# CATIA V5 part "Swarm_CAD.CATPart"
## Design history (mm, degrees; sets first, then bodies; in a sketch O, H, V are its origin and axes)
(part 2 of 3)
  Pad35: profile Sketch46, direction (0, -1, 0), length 15, mirrored extent
  Mirror19: of Pad35, about zx-plane
  Sketch47 on face of Mirror7, origin (0, 0, -275), H (1, 0, 0), V (0, -1, 0)
    line L1 (-1850, 565) -> (-1840, 565)
    line L2 (-1840, 565) -> (-1840, -565)
    line L3 (-1840, -565) -> (-1850, -565)
    line L4 (-1850, -565) -> (-1850, 565)
    point P2 (-1840, 565)
    point P3 (-1840, -565)
    reference projected line E1 (-2000, 665) -> (-2000, 406) from edge [end face of Pad1 | face of Mirror7]
    reference projected line E3 (2945.11, -665) -> (-2000, -665) from edge [face of Mirror7 | face of Pad28]
    reference projected line E4 (2945.11, 665) -> (-2000, 665) from edge [face of Pad28 | face of Mirror7]
    distance L4 E1 = 150
    distance L2 L4 = 10
    distance P3 E3 = 100
    distance P2 E4 = 100
    horizontal: L1 H, L3 H
    vertical: L2 V, L4 V
  Pad36: profile Sketch47, direction (0, 0, -1), length 60
  Sketch48 on face of Mirror17, origin (0, 0, -315), H (1, 0, 0), V (0, -1, 0)
    line L1 (-1750, -660) -> (-1750, -565)
    line L2 (-1750, -565) -> (-2040, -565)
    line L3 (-2040, -565) -> (-2040, -665)
    line L4 (-2040, -665) -> (-1750, -665)
    point P5 (-1750, -665)
    line L5 (-1750, -665) -> (-1750, -660)
    reference projected line E1 (-2000, -406) -> (-2000, -665) from edge [end face of Pad1 | face of Mirror7]
    reference projected line E4 (2945.11, -665) -> (-2000, -665) from edge [face of Mirror7 | face of Pad28]
    reference projected line E5 (-2000, -665) -> (-2000, -605) from edge [start face of Pad28 | face of Mirror17]
    reference projected line E6 (2945.11, -665) -> (-2000, -665) from edge [face of Mirror7 | face of Pad28]
    distance L3 E1 = 40
    distance L2 E4 = 100
    distance L1 E5 = 250
    distance L4 E6 = 0
    vertical: L1 V, L3 V
    horizontal: L2 H, L4 H
    coincidence: P5 L1
    parallelism: L5 L1
  Pad37: profile Sketch48, direction (0, 0, 1), length 81
  Mirror20: of Pad37, about zx-plane
  Sketch49 on face of Pad37, origin (0, 665, 0), H (-1, 0, 0), V (0, 0, 1)
    point P1 (1750, -275)
    line L1 (1750, -275) -> (1750, -315)
    line L2 (1750, -315) -> (1819.282, -315)
    line L3 (1819.282, -315) -> (1750, -275)
    reference projected line E1 (1880, -315) -> (1750, -315) from edge [face of Pad37 | face of Pad37]
    reference projected line E2 (-2945.11, -275) -> (2000, -275) from edge [face of Mirror7 | face of Pad37]
    reference projected line E3 (1750, -315) -> (1750, -234) from edge [face of Pad37 | face of Pad37 from Sketch48.L5]
    distance L2 E1 = 0
    distance P1 E2 = 0
    angle L1 L3 = 60
    vertical: L1 V
    horizontal: L2 H
    coincidence: L1 E3
  Pocket11: profile Sketch49, direction (0, -1, 0), up to face of Mirror20
  Plane5: type Offset, RefPlane end face of Pad1, Offset 60
  Sketch50 on Plane5, origin (-1940, 0, 0), H (0, 1, 0), V (0, 0, 1)
    line L1 (161.8482, -275) -> (149.7238, -282)
    line L2 (149.7238, -282) -> (147, -360)
    point P3 (147, -360)
    line L3 (147, -360) -> (147, -275)
    line L4 (147, -275) -> (161.8482, -275)
    reference projected line E1 (-665, -275) -> (-406, -275) from edge [end face of Pad1 | face of Mirror7]
    reference projected line E3 (-665, -275) -> (-406, -275) from edge [end face of Pad1 | face of Mirror7]
    axis line L5 (147, -270) -> (147, -400)
    point P5 (147, -270)
    distance L4 E1 = 0
    angle L2 L3 = 2
    angle L1 L4 = 30
    distance P3 E3 = 85
    length L1 = 14
    distance L3 V = 147
    vertical: L3 V, L5 V
    horizontal: L4 H
    coincidence: P5 L3
  Shaft1: profile Sketch50, axis Sketch50.L5, angle 360
  Mirror21: of Shaft1, about zx-plane
  Sketch51 on face of Mirror7, origin (0, 0, -275), H (1, 0, 0), V (0, -1, 0)
    line L1 (-1678, 31.5) -> (-1615, 31.5)
    line L2 (-1615, 31.5) -> (-1615, -31.5)
    line L3 (-1615, -31.5) -> (-1678, -31.5)
    line L4 (-1678, -31.5) -> (-1678, 31.5)
    reference projected line E1 (-2000, 665) -> (-2000, 406) from edge [end face of Pad1 | face of Mirror7]
    distance L1 L3 = 63
    distance L2 L4 = 63
    distance L4 E1 = 322
    distance L3 H = 31.5
    horizontal: L1 H, L3 H
    vertical: L2 V, L4 V
  Pad38: profile Sketch51, direction (0, 0, -1), length 50
  Chamfer5: length 50, angle 6, on edge [face of Pad38 from Sketch51.L2 | end face of Pad38]; edge [face of Pad38 from Sketch51.L4 | end face of Pad38]
  Plane6: type Offset, RefPlane face of Pad38 from Sketch51.L3, Offset 31.5
  Sketch52 on Plane6, origin (0, 0, 0), H (1, 0, 0), V (0, 0, 1)
    point P1 (-1646.5, -325)
    line L1 (-1646.5, -325) -> (-1646.5, -521)
    line L2 (-1646.5, -521) -> (-1628.5, -521)
    line L3 (-1628.5, -521) -> (-1621.5, -325)
    line L4 (-1621.5, -325) -> (-1646.5, -325)
    reference projected line E1 (-1615, -325) -> (-1678, -325) from edge [face of Pad38 from Sketch51.L1 | end face of Pad38]
    reference projected point E2 (-1678, -275) from vertex [face of Pad38 from Sketch51.L1 | face of Chamfer5 | face of Mirror7]
    reference projected line E3 (-1615, -275) -> (-1678, -275) from edge [face of Mirror7 | face of Pad38 from Sketch51.L1]
    axis line L5 (-1646.5, -300) -> (-1646.5, -600)
    point P5 (-1646.5, -300)
    distance L4 E1 = 0
    length L2 = 18
    distance P1 E2 H = 31.5
    distance L2 E3 = 246
    length L4 = 25
    vertical: L1 V, L5 V
    horizontal: L2 H, L4 H
    coincidence: P5 L1
  Shaft2: profile Sketch52, axis Sketch52.L5, angle 360
  Plane7: type Offset, RefPlane face of Mirror7, Offset 173, reversed
  Sketch53 on Plane7, origin (0, 0, -448), H (1, 0, 0), V (0, 1, 0)
    line L1 (-393, -191.5) -> (-487, -191.5)
    line L2 (-487, -191.5) -> (-487, -238.5)
    line L3 (-487, -238.5) -> (-393, -238.5)
    line L4 (-393, -238.5) -> (-393, -191.5)
    reference projected line E1 (-2000, 406) -> (-2000, 665) from edge [end face of Pad1 | face of Mirror7]
    length L2 = 47
    distance L4 L2 = 94
    distance L2 E1 = 1513
    distance L1 H = 191.5
    horizontal: L1 H, L3 H
    vertical: L2 V, L4 V
  Pad39: profile Sketch53, direction (0, 0, 1), length 300
  Sketch54 on start face of Pad39, origin (0, 0, -448), H (1, 0, 0), V (0, -1, 0)
    line L1 (-483.5, 235) -> (-443.5, 235)
    line L2 (-443.5, 235) -> (-443.5, 195)
    line L3 (-443.5, 195) -> (-483.5, 195)
    line L4 (-483.5, 195) -> (-483.5, 235)
    point P5 (-436.5, 235)
    line L5 (-436.5, 235) -> (-396.5, 235)
    line L6 (-396.5, 235) -> (-396.5, 195)
    line L7 (-396.5, 195) -> (-436.5, 195)
    line L8 (-436.5, 195) -> (-436.5, 235)
    point P7 (-396.5, 195)
    reference projected line E1 (-393, 238.5) -> (-393, 191.5) from edge [start face of Pad39 | face of Pad39 from Sketch53.L4]
    reference projected line E2 (-393, 191.5) -> (-487, 191.5) from edge [start face of Pad39 | face of Pad39 from Sketch53.L1]
    reference projected line E3 (-487, 191.5) -> (-487, 238.5) from edge [start face of Pad39 | face of Pad39 from Sketch53.L2]
    distance L6 E1 = 3.5
    length L8 = 40
    distance L7 E2 = 3.5
    distance L8 L6 = 40
    distance L4 E3 = 3.5
    distance L2 L4 = 40
    horizontal: L1 H, L3 H, L5 H, L7 H
    vertical: L2 V, L4 V, L6 V, L8 V
    coincidence: P5 L1, P7 L3
  Pad40: profile Sketch54, direction (0, 0, -1), length 3
  Plane8: type Offset, RefPlane start face of Pad39, Offset 32
  Sketch55 on Plane8, origin (0, 0, -416), H (1, 0, 0), V (0, 1, 0)
    line L1 (-383, -181.5) -> (-517, -181.5)
    line L2 (-517, -181.5) -> (-517, -248.5)
    line L3 (-517, -248.5) -> (-383, -248.5)
    line L4 (-383, -248.5) -> (-383, -181.5)
    reference projected line E1 (-487, -191.5) -> (-487, -238.5) from edge [start face of Pad39 | face of Pad39 from Sketch53.L2]
    reference projected line E2 (-393, -191.5) -> (-487, -191.5) from edge [start face of Pad39 | face of Pad39 from Sketch53.L1]
    reference projected line E3 (-487, -238.5) -> (-393, -238.5) from edge [start face of Pad39 | face of Pad39 from Sketch53.L3]
    reference projected line E4 (-393, -238.5) -> (-393, -191.5) from edge [start face of Pad39 | face of Pad39 from Sketch53.L4]
    distance L2 E1 = 30
    distance L1 E2 = 10
    distance L3 E3 = 10
    distance L4 E4 = 10
    horizontal: L1 H, L3 H
    vertical: L2 V, L4 V
  Pad41: profile Sketch55, direction (0, 0, 1), length 300
  Chamfer6: length 170, angle 8, on edge [start face of Pad41 | face of Pad41 from Sketch55.L2]
  Sketch56 on face of Mirror20, origin (0, -665, 0), H (1, 0, 0), V (0, 0, 1)
    point P1 (-365, -211)
    line L1 (-365, -211) -> (9, -211)
    point P2 (9, -211)
    line L2 (9, -211) -> (181, -250)
    point P3 (181, -250)
    line L3 (181, -250) -> (753, -250)
    line L4 (753, -250) -> (753, 29)
    line L5 (753, 29) -> (-365, 29)
    line L6 (-365, 29) -> (-365, -211)
    reference projected line E1 (2945.11, -275) -> (-2000, -275) from edge [face of Mirror20 | face of Mirror7]
    reference projected line E2 (-2010, 1) -> (-2010, -315) from edge [face of Pad34 from Sketch44.L3 | end face of Pad34]
    reference projected line E3 (682.5, 452.4746) -> (682.5, -2.8239) from edge [face of Pad2 | face of Pocket5 from Sketch28.L18]
    distance L1 E1 = 64
    distance L3 L1 = 39
    distance P3 P2 H = 172
    length L1 = 374
    distance P1 E2 = 1645
    distance L4 E3 = 70.5
    distance L5 L1 = 240
    horizontal: L1 H, L3 H, L5 H
    vertical: L4 V, L6 V
  Pad42: profile Sketch56, direction (0, 1, 0), length 50
  Mirror22: of Pad42, about zx-plane
  Sketch57 on face of Pad42, origin (0, -665, 0), H (1, 0, 0), V (0, 0, 1)
    line L1 (-780, 21.4391) -> (-780, -232)
    point P2 (-780, -232)
    line L2 (-780, -232) -> (-704, -232)
    point P3 (-704, -232)
    line L3 (-704, -232) -> (90, -71.9015)
    line L4 (90, -71.9015) -> (90, 21.4391)
    line L5 (90, 21.4391) -> (-780, 21.4391)
    reference projected line E1 (2945.11, -275) -> (-2000, -275) from edge [face of Pad42 | face of Mirror7]
    reference projected line E2 (2945.11, -275) -> (-2000, -275) from edge [face of Pad42 | face of Mirror7]
    reference projected point E3 (-679, -275) from vertex [face of Pocket2 from Sketch5.L3 | face of Pad1 from Sketch1.L8 | face of Pocket1 from Sketch4.L1]
    reference projected line E4 (710, 5.0715) -> (-679, -275) from edge [face of Pad42 | face of Pocket2 from Sketch5.L3]
    reference projected line E5 (-24, 30.4391) -> (-209, 30.4391) from edge [face of Pocket5 from Sketch28.L15 | face of Pad2]
    reference projected point E6 (-679, -275) from vertex [face of Pocket2 from Sketch5.L3 | face of Pad1 from Sketch1.L8 | face of Pocket1 from Sketch4.L1]
    distance L2 E2 = 43
    distance P3 E3 H = 25
    distance L4 L1 = 870
    distance L5 E5 = 9
    distance P2 E6 H = 101
    vertical: L1 V, L4 V
    horizontal: L2 H
    parallelism: L5 E1, L3 E4
  Pad43: profile Sketch57, direction (0, -1, 0), length 25
  Mirror23: of Pad43, about zx-plane
  Sketch58 on face of Pad42, origin (0, -665, 0), H (1, 0, 0), V (0, 0, 1)
    line L1 (-1666, -166.5) -> (-1596, -166.5)
    line L2 (-1596, -166.5) -> (-1596, -236.5)
    line L3 (-1596, -236.5) -> (-1666, -236.5)
    line L4 (-1666, -236.5) -> (-1666, -166.5)
    point P5 (-1493.5, -166.5)
    line L5 (-1493.5, -166.5) -> (-1423.5, -166.5)
    line L6 (-1423.5, -166.5) -> (-1423.5, -236.5)
    line L7 (-1423.5, -236.5) -> (-1493.5, -236.5)
    line L8 (-1493.5, -236.5) -> (-1493.5, -166.5)
    point P7 (-1423.5, -236.5)
    point P9 (-1381, -166.5)
    line L9 (-1381, -166.5) -> (-1311, -166.5)
    line L10 (-1311, -166.5) -> (-1311, -236.5)
    line L11 (-1311, -236.5) -> (-1381, -236.5)
    line L12 (-1381, -236.5) -> (-1381, -166.5)
    point P11 (-1311, -236.5)
    reference projected line E1 (-2010, 1) -> (-2010, -315) from edge [face of Pad34 from Sketch44.L3 | end face of Pad34]
    reference projected line E2 (-2010, 1) -> (-2010, -315) from edge [face of Pad34 from Sketch44.L3 | end face of Pad34]
    reference projected line E3 (2945.11, -275) -> (-2000, -275) from edge [face of Pad42 | face of Mirror7]
    line L13 (333, -141.5) -> (403, -141.5)
    line L14 (403, -141.5) -> (403, -211.5)
    line L15 (403, -211.5) -> (333, -211.5)
    line L16 (333, -211.5) -> (333, -141.5)
    line L17 (423, -141.5) -> (493, -141.5)
    line L18 (493, -141.5) -> (493, -211.5)
    line L19 (493, -211.5) -> (423, -211.5)
    line L20 (423, -211.5) -> (423, -141.5)
    point P19 (493, -211.5)
    reference projected line E4 (181, -250) -> (753, -250) from edge [face of Pad42 from Sketch56.L3 | start face of Pad42]
    reference projected line E5 (753, -250) -> (753, 29) from edge [face of Pad42 from Sketch56.L4 | face of Pad42]
    distance L4 E1 = 344
    distance L8 E2 = 516.5
    distance L6 L8 = 70
    distance L2 L4 = 70
    distance L12 L6 = 42.5
    distance L10 L12 = 70
    distance L11 E3 = 38.5
    distance L1 L3 = 70
    distance L15 E4 = 38.5
    distance L13 L15 = 70
    distance L14 L16 = 70
    distance L17 L19 = 70
    distance L20 L18 = 70
    distance L20 L14 = 20
    distance L18 E5 = 260
    horizontal: L1 H, L3 H, L5 H, L7 H, L9 H, L11 H, L13 H, L15 H, L17 H, L19 H
    vertical: L2 V, L4 V, L6 V, L8 V, L10 V, L12 V, L14 V, L16 V, L18 V, L20 V
    coincidence: P5 L1, P7 L3, P9 L1, P11 L3, P19 L15
  Pad44: profile Sketch58, direction (0, -1, 0), length 20
  Mirror24: of Pad44, about zx-plane
  Plane9: type Offset, RefPlane face of Pad42 from Sketch56.L4, Offset 43
  Sketch59 on Plane9, origin (710, 0, 0), H (0, -1, 0), V (0, 0, 1)
    line L1 (615, 5.0715) -> (615, -250)
    line L2 (615, -250) -> (532.5482, -250)
    line L3 (532.5482, -250) -> (209, -14.9285)
    point P4 (209, -14.9285)
    line L4 (209, -14.9285) -> (0, -14.9285)
    point P5 (0, -14.9285)
    line L5 (0, -14.9285) -> (0, 5.0715)
    line L6 (0, 5.0715) -> (615, 5.0715)
    reference projected line E1 (665, -250) -> (615, -250) from edge [face of Pad42 from Sketch56.L3 | face of Pad42 from Sketch56.L4]
    reference projected line E2 (615, -250) -> (615, 29) from edge [end face of Pad42 | face of Pad42 from Sketch56.L4]
    reference projected line E3 (665, 5.0715) -> (-665, 5.0715) from edge [face of Pocket2 from Sketch5.L3 | face of Pocket3 from Sketch6.L4]
    distance L2 E1 = 0
    distance L1 E2 = 0
    distance L6 E3 = 0
    distance L4 L6 = 20
    angle L3 L2 = 36
    distance P4 V = 209
    vertical: L1 V, L5 V
    horizontal: L2 H, L4 H, L6 H
    coincidence: P5 V
  Pad45: profile Sketch59, direction (-1, 0, 0), length 35
  Mirror25: of Pad45, about zx-plane
  Plane10: type Offset, RefPlane face of Pad37, Offset 38
  Sketch60 on Plane10, origin (0, 0, -277), H (1, 0, 0), V (0, 1, 0)
    line L1 (504, 615) -> (354, 615)
    line L2 (354, 615) -> (354, 465)
    line L3 (354, 465) -> (504, 465)
    line L4 (504, 465) -> (504, 615)
    reference projected line E1 (-2000, 406) -> (-2000, 665) from edge [end face of Pad1 | face of Mirror7]
    reference projected line E4 (181, 615) -> (753, 615) from edge [face of Mirror25 | face of Mirror22]
    distance L2 E1 = 2354
    distance L2 L4 = 150
    distance L1 L3 = 150
    distance L1 E4 = 0
    horizontal: L1 H, L3 H
    vertical: L2 V, L4 V
  Pad46: profile Sketch60, direction (0, 0, 1), length 350
  Sketch61 on start face of Pad46, origin (0, 0, -277), H (1, 0, 0), V (0, -1, 0)
    point P1 (428.7804, -474)
    line L1 (428.7804, -474) -> (363, -539.7804)
    point P2 (363, -539.7804)
    line L2 (363, -539.7804) -> (429.2196, -606)
    point P3 (429.2196, -606)
    line L3 (429.2196, -606) -> (495, -540.2196)
    point P4 (495, -540.2196)
    line L4 (495, -540.2196) -> (428.7804, -474)
    reference projected line E1 (504, -615) -> (354, -615) from edge [start face of Pad46 | face of Pad46 from Sketch60.L1]
    reference projected line E2 (354, -465) -> (504, -465) from edge [start face of Pad46 | face of Pad46 from Sketch60.L3]
    reference projected line E3 (504, -465) -> (504, -615) from edge [start face of Pad46 | face of Pad46 from Sketch60.L4]
    reference projected line E4 (354, -615) -> (354, -465) from edge [start face of Pad46 | face of Pad46 from Sketch60.L2]
    distance P3 E1 = 9
    distance P1 E2 = 9
    distance P4 E3 = 9
    distance P2 E4 = 9
    length L3 = 93.0275
    perpendicularity: L2 L1
    parallelism: L3 L1, L4 L2
  Pad47: profile Sketch61, direction (0, 0, -1), length 48
  Chamfer7: length 40, angle 40, on edge [face of Pad47 from Sketch61.L1 | end face of Pad47]; edge [face of Pad47 from Sketch61.L4 | end face of Pad47]; edge [face of Pad47 from Sketch61.L3 | end face of Pad47]; edge [face of Pad47 from Sketch61.L2 | end face of Pad47]
  Plane11: type Angle, RefPlane face of Pocket6 from Sketch29.L2, Direction edge [face of Pocket6 from Sketch29.L2 | face of Mirror1], Angle 142
  Sketch62 on Plane11, origin (1777.8711, -1279.5012, -929.612), H (0.5498, 0.8351, 0.0175), V (0.2982, -0.2158, 0.9298)
    line L1 (1470, 1267) -> (1564, 1267)
    line L2 (1564, 1267) -> (1564, 1220)
    line L3 (1564, 1220) -> (1470, 1220)
    line L4 (1470, 1220) -> (1470, 1267)
    distance L1 L3 = 47
    distance L2 L4 = 94
    horizontal: L1 H, L3 H
    vertical: L2 V, L4 V
  Pad48: profile Sketch62, direction (-0.7802, 0.506, 0.3676), length 380
  Sketch63 on start face of Pad48, origin (1854.1669, -1202.5034, -873.6698), H (0.5441, 0.839, 0), V (0.3085, -0.2, 0.93)
    line L1 (1343.3933, 1230.7969) -> (1383.3863, 1231.5482)
    line L2 (1383.3863, 1231.5482) -> (1384.1376, 1191.5553)
    line L3 (1384.1376, 1191.5553) -> (1344.1446, 1190.804)
    line L4 (1344.1446, 1190.804) -> (1343.3933, 1230.7969)
    point P5 (1390.385, 1231.6797)
    line L5 (1390.385, 1231.6797) -> (1430.378, 1232.4309)
    line L6 (1430.378, 1232.4309) -> (1431.1293, 1192.438)
    line L7 (1431.1293, 1192.438) -> (1391.1363, 1191.6867)
    line L8 (1391.1363, 1191.6867) -> (1390.385, 1231.6797)
    point P7 (1431.1293, 1192.438)
    reference projected line E1 (1434.6944, 1189.0043) -> (1433.8116, 1235.9961) from edge [face of Pad48 from Sketch62.L2 | start face of Pad48]
    reference projected line E2 (1339.8282, 1234.2306) -> (1340.711, 1187.2389) from edge [face of Pad48 from Sketch62.L4 | start face of Pad48]
    reference projected line E3 (1433.8116, 1235.9961) -> (1339.8282, 1234.2306) from edge [face of Pad48 from Sketch62.L1 | start face of Pad48]
    distance L2 L4 = 40
    distance L8 L6 = 40
    distance L6 E1 = 3.5
    distance L4 E2 = 3.5
    distance L1 E3 = 3.5
    distance L3 L1 = 40
    distance L7 L5 = 40
    coincidence: P5 L1, P7 L3
  Pad49: profile Sketch63, direction (0.7802, -0.506, -0.3676), length 3
  Mirror26: of Pad48, about zx-plane
  Mirror27: of Pad49, about zx-plane
  Sketch64 on face of Mirror1, origin (2945.11, 0, 0), H (0, 1, 0), V (0, 0, 1)
    line L1 (-128.815, 480.931) -> (128.815, 480.931)
    line L2 (128.815, 480.931) -> (128.815, 295.2187)
    line L3 (128.815, 295.2187) -> (-128.815, 295.2187)
    line L4 (-128.815, 295.2187) -> (-128.815, 480.931)
    reference projected point E1 (113.815, 470.931) from vertex [face of Pocket4 from Sketch2.L1 | face of Mirror1 | face of Mirror1]
    reference projected point E2 (-113.815, 470.931) from vertex [face of Mirror4 | face of Pad2 | face of Mirror1]
    reference projected line E3 (62.5, 470.931) -> (-62.5, 470.931) from edge [face of Pad1 from Sketch1.L2 | face of Mirror2]
    reference projected line E4 (-328.1347, 315.2187) -> (328.1347, 315.2187) from edge [face of Pocket3 from Sketch6.L4 | face of Mirror1]
    distance L2 E1 = 15
    distance E2 L4 = 15
    distance L1 E3 = 10
    distance L3 E4 = 20
    horizontal: L1 H, L3 H
    vertical: L2 V, L4 V
  Pad50: profile Sketch64, direction (1, 0, 0), length 103
  Sketch65 on face of Pocket3 from Sketch6.L4, origin (12.7222, 0, -91.6838), H (0, 1, 0), V (0.9905, 0, 0.1374)
    line L1 (-128.815, 2960.4844) -> (128.815, 2960.4844)
    line L2 (128.815, 2960.4844) -> (128.815, 2160.4844)
    line L3 (128.815, 2160.4844) -> (-128.815, 2160.4844)
    line L4 (-128.815, 2160.4844) -> (-128.815, 2960.4844)
    reference projected line E1 (-328.1347, 2960.4844) -> (328.1347, 2960.4844) from edge [face of Pocket3 from Sketch6.L4 | face of Mirror1]
    reference projected line E2 (-128.815, 2957.7355) -> (-128.815, 3059.758) from edge [face of Pad50 from Sketch64.L3 | face of Pad50 from Sketch64.L4]
    reference projected line E3 (128.815, 2957.7355) -> (128.815, 3059.758) from edge [face of Pad50 from Sketch64.L2 | face of Pad50 from Sketch64.L3]
    distance L1 E1 = 0
    distance L4 E2 = 0
    distance L2 E3 = 0
    distance L3 L1 = 800
    horizontal: L1 H, L3 H
    vertical: L2 V, L4 V
  Pocket12: profile Sketch65, direction (-0.1374, 0, 0.9905), length 15
  Plane12: type Offset, RefPlane face of Pad7, Offset 1585
  Sketch66 on Plane12, origin (5308.6795, 0, -1274.5012), H (0, -1, 0), V (0.2334, 0, 0.9724)
    point P1 (120, 1145.4414)
    line L1 (120, 1145.4414) -> (84.0815, 1238.7681)
    line L2 (0.0875, 1296.4414) -> (-0.0875, 1296.4414)
    line L3 (-84.0815, 1238.7681) -> (-120, 1145.4414)
    point P2 (-120, 1145.4414)
    line L4 (-120, 1145.4414) -> (120, 1145.4414)
    arc A1 centre (0.0875, 1206.4414) radius 90 from (84.0815, 1238.7681) to (0.0875, 1296.4414) ccw
    arc A2 centre (-0.0875, 1206.4414) radius 90 from (-0.0875, 1296.4414) to (-84.0815, 1238.7681) ccw
    reference intersected line E1 (-62.5, 1145.4414) -> (62.5, 1145.4414) from face of Mirror2
    reference intersected line E2 (-62.5, 1145.4414) -> (62.5, 1145.4414) from face of Mirror2
    reference intersected line E3 through (0, 0) direction (0, -1) from zx-plane
    radius A1 = 90
    radius A2 = 90
    distance L4 E1 = 0
    distance L2 E2 = 151
    distance P2 P1 = 240
    distance P2 E3 = 120
    length L1 = 100
    length L3 = 100
    horizontal: L2 H, L4 H
    tangency: A1 L1, A1 L2, A2 L2, A2 L3
  Pad51: profile Sketch66, direction (-0.9724, 0, 0.2334), length 260
  Sketch67 on start face of Pad51, origin (5308.6795, 0, -1274.5012), H (0, 1, 0), V (0.2334, 0, 0.9724)
    line L1 (-85.3658, 1165.8292) -> (-46.1955, 1267.6048)
    line L2 (-4.1986, 1296.4414) -> (4.1986, 1296.4414)
    line L3 (46.1955, 1267.6048) -> (85.3658, 1165.8292)
    point P1 (91.288, 1150.4414)
    arc A1 centre (-4.1986, 1251.4414) radius 45 from (-46.1955, 1267.6048) to (-4.1986, 1296.4414) cw
    arc A2 centre (4.1986, 1251.4414) radius 45 from (4.1986, 1296.4414) to (46.1955, 1267.6048) cw
    reference projected line E1 (86, 1145.4414) -> (63.5, 1145.4414) from edge [face of Mirror2 | end face of Pad6]
    arc A3 centre (71.3668, 1160.4414) radius 15 from (85.3658, 1165.8292) to (71.3668, 1145.4414) cw
    arc A4 centre (-71.3668, 1160.4414) radius 15 from (-71.3668, 1145.4414) to (-85.3658, 1165.8292) cw
    reference projected line E2 (-114.6804, 1159.2632) -> (-78.762, 1252.5898) from edge [start face of Pad51 | face of Pad51 from Sketch66.L1]
    reference projected line E3 (78.762, 1252.5898) -> (114.6804, 1159.2632) from edge [start face of Pad51 | face of Pad51 from Sketch66.L3]
    line L4 (-160, 1345.4414) -> (160, 1345.4414)
    line L5 (160, 1345.4414) -> (160, 1145.4414)
    line L6 (-160, 1145.4414) -> (-160, 1345.4414)
    line L7 (-160, 1145.4414) -> (-71.3668, 1145.4414)
    line L8 (71.3668, 1145.4414) -> (160, 1145.4414)
    reference projected line E4 (71.473, 1145.4414) -> (-71.473, 1145.4414) from edge [start face of Pad51 | face of Mirror2]
    reference projected line E5 (71.473, 1145.4414) -> (-71.473, 1145.4414) from edge [start face of Pad51 | face of Mirror2]
    reference intersected line E6 through (0, 0) direction (0, 1) from zx-plane
    reference intersected line E7 through (0, 0) direction (0, 1) from zx-plane
    reference intersected line E8 (-62.5, 1145.4414) -> (62.5, 1145.4414) from face of Mirror2
    reference projected point E9 (0.0875, 1296.4414) from vertex [face of Pad51 from Sketch66.L2 | face of Pad51 from Sketch66.A2 | start face of Pad51]
    radius A1 = 45
    radius A2 = 45
    distance P1 E1 = 5
    radius A3 = 15
    radius A4 = 15
    distance L1 E2 = 25
    distance L3 E3 = 25
    distance L8 E4 = 0
    distance L7 E5 = 0
    distance L6 E6 = 160
    distance L5 E7 = 160
    distance L4 E8 = 200
    distance L2 E9 = 0
    horizontal: L2 H, L4 H
    tangency: A1 L1, A1 L2, A2 L2, A2 L3, A3 L3, A4 L1, A3 L8, A4 L7
    coincidence: L3 P1
    vertical: L5 V, L6 V
  Pocket13: profile Sketch67, direction (-0.9724, 0, 0.2334), length 50
  Sketch68 on end face of Pocket13, origin (5260.0611, 0, -1262.8289), H (0, 1, 0), V (0.2334, 0, 0.9724)
    point P1 (120, 1145.4414)
    line L1 (120, 1145.4414) -> (71.7414, 1061.8551)
    line L2 (71.7414, 1061.8551) -> (71.7414, 1145.4414)
    line L3 (71.7414, 1145.4414) -> (120, 1145.4414)
    reference intersected line E1 (71.7414, 1145.4414) -> (71.7414, 1005.5379) from end face of Pad6
    reference projected line E2 (-120, 1145.4414) -> (-71.7414, 1145.4414) from edge [face of Pad51 from Sketch66.L4 | end face of Pocket13]
    reference projected point E4 (120, 1145.4414) from vertex [face of Pad51 from Sketch66.L3 | face of Pad51 from Sketch66.L4 | end face of Pocket13]
    distance L2 E1 = 0
    distance L3 E2 = 0
    distance P1 E4 = 0
    angle L1 L2 = 30
    vertical: L2 V
    horizontal: L3 H
  Pad52: profile Sketch68, direction (-0.9724, 0, 0.2334), length 90
  Mirror28: of Pad52, about zx-plane
  Sketch69 on end face of Pad51, origin (5055.8634, 0, -1213.8054), H (0, -1, 0), V (0.2334, 0, 0.9724)
    point P1 (-60, 1145.4414)
    line L1 (-60, 1145.4414) -> (60, 1145.4414)
    line L2 (60, 1145.4414) -> (48.2288, 1183.6702)
    line L3 (10, 1211.8989) -> (-10, 1211.8989)
    line L4 (-48.2288, 1183.6702) -> (-60, 1145.4414)
    arc A1 centre (-10, 1171.8989) radius 40 from (-48.2288, 1183.6702) to (-10, 1211.8989) cw
    arc A2 centre (10, 1171.8989) radius 40 from (10, 1211.8989) to (48.2288, 1183.6702) cw
    reference projected line E1 (-72.8689, 1145.4414) -> (72.8689, 1145.4414) from edge [face of Mirror2 | end face of Pad51]
    reference intersected line E2 through (0, 0) direction (0, -1) from zx-plane
    radius A1 = 40
    radius A2 = 40
    distance L1 E1 = 0
    length L1 = 120
    distance P1 E2 = 60
    length L3 = 20
    length L4 = 40
    length L2 = 40
    horizontal: L1 H, L3 H
    tangency: A1 L4, A1 L3, A2 L3, A2 L2
  Pad53: profile Sketch69, direction (-0.9724, 0, 0.2334), length 400
  Sketch70 on end face of Pad53, origin (4666.9154, 0, -1120.4273), H (0, -1, 0), V (0.2334, 0, 0.9724)
    line L1 (0, 1203.6872) -> (0, 1165.4414)
    line L2 (0, 1165.4414) -> (70, 1165.4414)
    line L3 (70, 1165.4414) -> (241, 1066.7145)
    point P4 (241, 1066.7145)
    line L4 (241, 1066.7145) -> (241, 1084.035)
    line L5 (241, 1084.035) -> (50, 1194.3089)
    line L6 (15, 1203.6872) -> (0, 1203.6872)
    reference projected line E1 (-60, 1145.4414) -> (60, 1145.4414) from edge [face of Mirror2 | end face of Pad53]
    reference intersected line E2 through (0, 0) direction (0, -1) from zx-plane
    arc A1 centre (15, 1133.6872) radius 70 from (15, 1203.6872) to (50, 1194.3089) cw
    reference intersected line E3 through (0, 0) direction (0, -1) from zx-plane
    angle L3 L4 = 60
    distance L2 E1 = 20
    distance L5 L3 = 15
    distance P4 E2 = 241
    radius A1 = 70
    distance L1 E3 = 0
    length L3 = 197.4538
    length L6 = 15
    vertical: L1 V, L4 V
    horizontal: L2 H, L6 H
    tangency: A1 L6, A1 L5
  Pad54: profile Sketch70, direction (-0.9724, 0, 0.2334), length 175
  Mirror29: of Pad54, about zx-plane
  Sketch71 on face of Mirror29, origin (280.9952, 0, 1170.4292), H (0, 1, 0), V (-0.9724, 0, 0.2334)
    line L1 (-50, -4709.5267) -> (50, -4709.5267)
    line L2 (50, -4709.5267) -> (50, -4799.5267)
    line L3 (50, -4799.5267) -> (-50, -4799.5267)
    line L4 (-50, -4799.5267) -> (-50, -4709.5267)
    reference projected line E1 (50, -4624.5267) -> (15, -4624.5267) from edge [face of Mirror29 | face of Mirror29]
    reference projected line E2 (241, -4799.5267) -> (50, -4799.5267) from edge [face of Mirror29 | face of Mirror29]
    distance L1 E1 = 85
    distance L3 E2 = 0
    distance L2 V = 50
    distance L4 V = 50
    horizontal: L1 H, L3 H
    vertical: L2 V, L4 V
  Pad55: profile Sketch71, direction (-0.2334, 0, -0.9724), up to face of Mirror2
  Sketch72 on face of Pad55 from Sketch71.L4, origin (0, -50, 0), H (1, 0, 0), V (0, 0, 1)
    line L1 (4970.5669, 161.2997) -> (5036.8289, 86.4041)
    line L2 (5036.8289, 86.4041) -> (4976.9124, 33.3945)
    line L3 (4976.9124, 33.3945) -> (4858.208, 61.8929)
    point P4 (4858.208, 61.8929)
    line L4 (4858.208, 61.8929) -> (4970.5669, 161.2997)
    reference projected line E1 (2945.1124, 470.9305) -> (7020.0521, -507.376) from edge [face of Mirror2 | face of Mirror2]
    reference projected line E2 (4945.7213, 40.8828) -> (4858.208, 61.8929) from edge [face of Pad55 from Sketch71.L4 | face of Pad54 from Sketch70.L5]
    reference projected line E3 (4860.3973, 71.012) -> (4858.208, 61.8929) from edge [face of Pad55 from Sketch71.L1 | face of Pad55 from Sketch71.L4]
    angle L1 E1 = 145
    distance L3 E2 = 0
    length L2 = 80
    distance L4 L2 = 100
    distance P4 E3 = 0
    perpendicularity: L2 L1
  Pad56: profile Sketch72, direction (0, 1, 0), length 100
  Sketch73 on face of Pad56 from Sketch72.L1, origin (2868.212, 0, 2537.5796), H (0, 1, 0), V (-0.6626, 0, 0.749)
    line L1 (-90, -3132.791) -> (-90, -3312.791)
    line L2 (-90, -3312.791) -> (90, -3312.791)
    line L3 (90, -3312.791) -> (90, -3132.791)
    line L4 (90, -3132.791) -> (-90, -3132.791)
    reference projected line E1 (-50, -3172.791) -> (50, -3172.791) from edge [face of Pad56 from Sketch72.L1 | face of Pad56 from Sketch72.L4]
    reference projected line E2 (-50, -3272.791) -> (50, -3272.791) from edge [face of Pad56 from Sketch72.L2 | face of Pad56 from Sketch72.L1]
    reference projected line E3 (-50, -3272.791) -> (-50, -3172.791) from edge [face of Pad56 from Sketch72.L1 | start face of Pad56]
    reference projected line E4 (50, -3272.791) -> (50, -3172.791) from edge [end face of Pad56 | face of Pad56 from Sketch72.L1]
    distance E1 L4 = 40
    distance E2 L2 = 40
    distance L1 E3 = 40
    distance L3 E4 = 40
    vertical: L1 V, L3 V
    horizontal: L2 H, L4 H
  Pad57: profile Sketch73, direction (0.749, 0, 0.6626), length 180
  Sketch74 on face of Pad57 from Sketch73.L1, origin (0, -90, 0), H (1, 0, 0), V (0, 0, 1)
    point P1 (5030.2027, 93.8937)
    line L1 (5030.2027, 93.8937) -> (5198.1457, 175.7175)
    point P2 (5198.1457, 175.7175)
    line L2 (5198.1457, 175.7175) -> (5078.8741, 310.5295)
    point P3 (5078.8741, 310.5295)
    line L3 (5078.8741, 310.5295) -> (4977.1931, 153.8101)
    point P4 (4977.1931, 153.8101)
    reference projected point E1 (5078.8741, 310.5295) from vertex [face of Pad57 from Sketch73.L4 | face of Pad57 from Sketch73.L1 | end face of Pad57]
    reference projected point E2 (5198.1457, 175.7175) from vertex [face of Pad57 from Sketch73.L2 | face of Pad57 from Sketch73.L1 | end face of Pad57]
    reference projected point E3 (5063.3337, 56.4459) from vertex [face of Pad57 from Sketch73.L2 | face of Pad57 from Sketch73.L1 | start face of Pad57]
    reference projected point E4 (4944.0621, 191.2579) from vertex [face of Pad57 from Sketch73.L4 | face of Pad57 from Sketch73.L1 | start face of Pad57]
    line L4 (4977.1931, 153.8101) -> (4924.8671, 212.9539)
    line L5 (4924.8671, 212.9539) -> (5081.0839, 351.163)
    line L6 (5081.0839, 351.163) -> (5238.7499, 172.9539)
    line L7 (5238.7499, 172.9539) -> (5082.5331, 34.7449)
    point P8 (5082.5331, 34.7449)
    line L8 (5082.5331, 34.7449) -> (5030.2027, 93.8937)
    reference projected line E5 (4952.1613, 198.4235) -> (5086.9733, 317.6951) from edge [face of Pad57 from Sketch73.L1 | face of Pad57 from Sketch73.L4]
    reference intersected line E6 (5070.7749, 319.684) -> (5190.0466, 184.8719) from end face of Pad57
    reference projected line E7 (5071.4329, 63.6114) -> (5206.2449, 182.883) from edge [face of Pad57 from Sketch73.L2 | face of Pad57 from Sketch73.L1]
    distance P3 E1 = 0
    distance P2 E2 = 0
    distance E3 P1 = 50
    distance P4 E4 = 50
    length L7 = 208.5796
    distance L5 E5 = 28.9684
    distance L6 E6 = 28.5796
    distance L7 E7 = 28.9749
    parallelism: L4 L2, L6 L2, L7 L5, L8 L2
    perpendicularity: L5 L2
    coincidence: P8 L4
  Pocket14: profile Sketch74, direction (0, 1, 0), length 180
  Sketch75 on face of Pad56 from Sketch72.L4, origin (2102.3549, 0, -2376.2799), H (0, -1, 0), V (0.749, 0, 0.6626)
    point P1 (-90, 4009.6149)
    line L1 (-90, 4009.6149) -> (-40, 3829.6149)
    point P2 (-40, 3829.6149)
    point P3 (40, 3829.6149)
    line L2 (40, 3829.6149) -> (90, 4009.6149)
    point P4 (90, 4009.6149)
    line L3 (90, 4009.6149) -> (-90, 4009.6149)
    reference projected line E1 (90, 4009.6149) -> (-90, 4009.6149) from edge [face of Pocket14 from Sketch74.L3 | face of Pocket14]
    line L4 (-40, 3829.6149) -> (-120, 3829.6149)
    line L5 (-120, 3829.6149) -> (-120, 4024.6149)
    line L6 (-120, 4024.6149) -> (100, 4024.6149)
    line L7 (100, 4024.6149) -> (100, 3829.6149)
    point P8 (100, 3829.6149)
    line L8 (100, 3829.6149) -> (40, 3829.6149)
    reference projected line E2 (-90, 3829.6149) -> (-90, 4009.6149) from edge [face of Pocket14 from Sketch74.L3 | face of Pad57 from Sketch73.L3]
    reference projected line E3 (90, 3829.6149) -> (90, 4009.6149) from edge [face of Pad57 from Sketch73.L1 | face of Pocket14 from Sketch74.L3]
    reference projected point E4 (-90, 4009.6149) from vertex [face of Pocket14 from Sketch74.L3 | face of Pocket14 | face of Pad57 from Sketch73.L3]
    reference projected point E5 (90, 4009.6149) from vertex [face of Pocket14 from Sketch74.L3 | face of Pocket14 | face of Pad57 from Sketch73.L1]
    reference intersected line E6 (-90, 3865.6149) -> (90, 3865.6149) from face of Pocket14 from Sketch74.L3
    reference projected line E7 (90, 4009.6149) -> (-90, 4009.6149) from edge [face of Pocket14 from Sketch74.L3 | face of Pocket14]
    reference projected line E8 (90, 3829.6149) -> (90, 4009.6149) from edge [face of Pad57 from Sketch73.L1 | face of Pocket14 from Sketch74.L3]
    reference projected line E9 (-90, 3829.6149) -> (-90, 4009.6149) from edge [face of Pocket14 from Sketch74.L3 | face of Pad57 from Sketch73.L3]
    distance L3 E1 = 0
    distance P2 E2 = 50
    distance P3 E3 = 50
    distance P1 E4 = 0
    distance P4 E5 = 0
    angle L1 E6 = 74.4759
    distance L6 E7 = 15
    distance L7 E8 = 10
    distance L5 E9 = 30
    horizontal: L3 H, L4 H, L6 H, L8 H
    vertical: L5 V, L7 V
    coincidence: P8 L4
  Pocket15: profile Sketch75, direction (0.6626, 0, -0.749), length 180
  Sketch76 on face of Pad55, origin (280.9952, 0, 1170.4292), H (0, 1, 0), V (-0.9724, 0, 0.2334)
    point P1 (0, -4696.0934)
    line L1 (0, -4696.0934) -> (-74.8956, -4629.8314)
    line L2 (-74.8956, -4629.8314) -> (-141.1576, -4704.727)
    line L3 (-141.1576, -4704.727) -> (-66.262, -4770.989)
    line L4 (-66.262, -4770.989) -> (0, -4696.0934)
    reference projected line E1 (-50, -4716.0934) -> (50, -4716.0934) from edge [face of Pad56 from Sketch72.L4 | face of Pad55]
    length L4 = 100
    angle L4 V = 41.5
    distance P1 E1 = 20
    distance L2 L4 = 100
    coincidence: P1 V
    perpendicularity: L2 L1
    parallelism: L3 L1
  Pad58: profile Sketch76, direction (-0.2334, 0, -0.9724), length 30
  Plane13: type Angle, RefPlane face of Pad58 from Sketch76.L2, Direction edge [face of Pad58 from Sketch76.L2 | face of Pad58], Angle 135
  Sketch77 on Plane13, origin (371.4312, 677.0704, -1018.8798), H (0.8767, -0.481, 0), V (0.3833, 0.6987, 0.604)
    line L1 (4258.3254, 1930.835) -> (4229.3806, 1835.1157)
    line L2 (4229.3806, 1835.1157) -> (4325.0999, 1806.1709)
    line L3 (4325.0999, 1806.1709) -> (4354.0447, 1901.8902)
    line L4 (4354.0447, 1901.8902) -> (4258.3254, 1930.835)
    reference projected line E1 (4226.6493, 1835.9416) -> (4322.3687, 1806.9968) from edge [face of Pad58 from Sketch76.L2 | start face of Pad58]
    reference projected line E2 (4252.5789, 1911.8316) -> (4232.1118, 1844.1478) from edge [face of Pad58 from Sketch76.L1 | face of Pad58]
    reference projected line E3 (4327.8312, 1815.203) -> (4348.2983, 1882.8868) from edge [face of Pad58 from Sketch76.L3 | start face of Pad58]
    length L2 = 100
    length L3 = 100
    distance L3 E3 = 0
    parallelism: L3 L1, L4 L2, L1 E2
    coincidence: L2 E1
  Pad59: profile Sketch77, direction (-0.2905, -0.5296, 0.7969), length 18, mirrored extent
  Plane14: type Offset, RefPlane face of Pad59, Offset 50
  Sketch78 on Plane14, origin (2597.8315, -2363.6757, -623.6842), H (-0.673, -0.7397, 0), V (0.1293, -0.1177, 0.9846)
    point P1 (-3266.1794, 812.3634)
    line L1 (-3266.1794, 812.3634) -> (-3120.4845, 706.661)
    line L2 (-3120.4845, 706.661) -> (-3014.7821, 852.3559)
    line L3 (-3014.7821, 852.3559) -> (-3160.477, 958.0583)
    line L4 (-3160.477, 958.0583) -> (-3266.1794, 812.3634)
    reference projected line E1 (-3247.3055, 770.2624) -> (-3226.1651, 799.4014) from edge [face of Pad59 from Sketch77.L1 | face of Pad59 from Sketch77.L4]
    reference projected line E2 (-3241.4405, 794.4151) -> (-3160.4988, 735.6916) from edge [face of Pad59 from Sketch77.L1 | end face of Pad59]
    distance L2 L4 = 180
    distance L3 L1 = 180
    distance P1 E1 = 40
    perpendicularity: L2 L1
    coincidence: L1 E2
  Pad60: profile Sketch78, direction (-0.7283, 0.6626, 0.1748), length 90, mirrored extent
  Sketch79 on end face of Pad60, origin (2532.2879, -2304.0399, -607.9485), H (-0.673, -0.7397, 0), V (0.1293, -0.1177, 0.9846)
    line L1 (-3157.2695, 948.1537) -> (-3221.6615, 780.0654)
    point P2 (-3221.6615, 780.0654)
    line L2 (-3221.6615, 780.0654) -> (-3293.3369, 832.0662)
    line L3 (-3293.3369, 832.0662) -> (-3162.0103, 1011.1007)
    line L4 (-3162.0103, 1011.1007) -> (-2965.8238, 868.7664)
    line L5 (-2965.8238, 868.7664) -> (-3097.1504, 689.732)
    point P6 (-3097.1504, 689.732)
    line L6 (-3097.1504, 689.732) -> (-3165.0024, 738.9589)
    point P7 (-3165.0024, 738.9589)
    line L7 (-3165.0024, 738.9589) -> (-3025.1931, 852.3316)
    line L8 (-3025.1931, 852.3316) -> (-3157.2695, 948.1537)
    reference projected line E1 (-3273.8171, 817.9045) -> (-3128.1222, 712.2022) from edge [face of Pad60 from Sketch78.L1 | end face of Pad60]
    reference projected line E2 (-3247.3055, 770.2624) -> (-3226.1651, 799.4014) from edge [face of Pad59 | face of Pad59 from Sketch77.L4]
    reference projected line E3 (-3166.3639, 711.5388) -> (-3145.2234, 740.6778) from edge [face of Pad59 from Sketch77.L2 | face of Pad59]
    reference projected line E4 (-3022.4198, 857.8971) -> (-3168.1147, 963.5995) from edge [face of Pad60 from Sketch78.L3 | end face of Pad60]
    reference projected line E5 (-3112.8468, 717.1884) -> (-3007.1444, 862.8833) from edge [face of Pad60 from Sketch78.L2 | end face of Pad60]
    length L7 = 180
    distance L6 E1 = 0
    distance P2 E2 = 15
    distance P7 E3 = 15
    length L1 = 180
    angle L1 L2 = 75
    length L3 = 222.036
    distance L4 L8 = 48.1663
    distance L3 L5 = 242.3769
    angle L5 L7 = 165.3
    distance P6 E5 = 28.8283
    coincidence: P6 L2
    parallelism: L6 L2, L8 E4
  Pocket16: profile Sketch79, direction (0.7283, -0.6626, -0.1748), up to start face of Pad60
  Sketch80 on face of Pad59 from Sketch77.L4, origin (1912.1212, 1631.5379, 1781.2575), H (-0.6491, 0.7607, 0), V (-0.4398, -0.3753, 0.8159)
    point P1 (-3339.3594, -1845.0643)
    line L1 (-3339.3594, -1845.0643) -> (-3163.5408, -1806.492)
    point P2 (-3163.5408, -1806.492)
    line L2 (-3163.5408, -1806.492) -> (-3180.0052, -1988.1057)
    point P3 (-3180.0052, -1988.1057)
    point P4 (-3248.3791, -2003.1061)
    line L3 (-3248.3791, -2003.1061) -> (-3339.3594, -1845.0643)
    reference projected line E1 (-3160.4263, -2007.351) -> (-3168.1407, -1972.1873) from edge [face of Pad59 | face of Pad59 from Sketch77.L4]
    reference projected point E2 (-3263.0306, -2006.3204) from vertex [face of Pad59 from Sketch77.L4 | face of Pocket16 from Sketch79.L2 | face of Pad59]
    line L4 (-3180.0052, -1988.1057) -> (-3124.3293, -1975.8911)
    line L5 (-3124.3293, -1975.8911) -> (-3163.7302, -1796.2957)
    line L6 (-3163.7302, -1796.2957) -> (-3343.4559, -1835.7252)
    line L7 (-3343.4559, -1835.7252) -> (-3304.055, -2015.3206)
    point P8 (-3304.055, -2015.3206)
    line L8 (-3304.055, -2015.3206) -> (-3248.3791, -2003.1061)
    reference projected line E3 (-3260.2435, -2005.709) -> (-3162.5665, -1984.2799) from edge [face of Pad59 from Sketch77.L4 | face of Pocket16 from Sketch79.L2]
    reference projected point E4 (-3339.3594, -1845.0643) from vertex [face of Pocket16 from Sketch79.L8 | start face of Pad60 | face of Pocket16 from Sketch79.L1]
    reference projected point E5 (-3163.5408, -1806.492) from vertex [face of Pocket16 from Sketch79.L8 | end face of Pad60 | face of Pocket16 from Sketch79.L1]
    reference projected line E6 (-3129.0699, -1963.6157) -> (-3166.3279, -1793.7879) from edge [end face of Pad60 | face of Pocket16 from Sketch79.L1]
    reference projected line E7 (-3304.8885, -2002.188) -> (-3342.1465, -1832.3603) from edge [start face of Pad60 | face of Pocket16 from Sketch79.L7]
    distance P3 E1 = 15
    distance P4 E2 = 15
    distance L5 E6 = 2
    distance L6 L1 = 10
    distance L7 E7 = 2
    parallelism: L4 L1, L8 L1
    perpendicularity: L5 L1
    coincidence: P8 L4, L8 E3, P1 E4, P2 E5
  Pocket17: profile Sketch80, direction (-0.6207, -0.5296, -0.5782), length 110, mirrored extent
  Sketch81 on end face of Pocket17, origin (1843.8477, 1573.2829, 1717.6566), H (-0.6491, 0.7607, 0), V (-0.4398, -0.3753, 0.8159)
    line L1 (-3146.2764, -1885.1859) -> (-3171.17, -1890.6472)
    line L2 (-3171.17, -1890.6472) -> (-3163.5408, -1806.492)
    line L3 (-3163.5408, -1806.492) -> (-3146.2764, -1885.1859)
    point P4 (-3339.3594, -1845.0643)
    line L4 (-3339.3594, -1845.0643) -> (-3297.2014, -1918.2969)
    line L5 (-3297.2014, -1918.2969) -> (-3322.095, -1923.7582)
    line L6 (-3322.095, -1923.7582) -> (-3339.3594, -1845.0643)
    reference projected line E1 (-3339.3594, -1845.0643) -> (-3322.095, -1923.7582) from edge [start face of Pad60 | end face of Pocket17]
    reference projected point E2 (-3339.3594, -1845.0643) from vertex [start face of Pad60 | face of Pocket17 from Sketch80.L3 | face of Pocket17 | end face of Pocket17]
    reference projected line E3 (-3248.3791, -2003.1061) -> (-3339.3594, -1845.0643) from edge [face of Pocket17 from Sketch80.L3 | end face of Pocket17]
    reference projected line E4 (-3171.17, -1890.6472) -> (-3146.2764, -1885.1859) from edge [face of Pocket16 from Sketch79.L7 | end face of Pocket17]
    reference projected line E6 (-3163.5408, -1806.492) -> (-3180.0052, -1988.1057) from edge [face of Pocket17 from Sketch80.L2 | end face of Pocket17]
    reference projected line E7 (-3163.5408, -1806.492) -> (-3146.2764, -1885.1859) from edge [end face of Pocket17 | end face of Pad60]
    reference projected line E8 (-3171.17, -1890.6472) -> (-3146.2764, -1885.1859) from edge [face of Pocket16 from Sketch79.L7 | end face of Pocket17]
    coincidence: L6 E1, P4 E2, L4 E3, L5 E4, L2 E6, L3 E7, L1 E8
  Pocket18: profile Sketch81, direction (-0.6207, -0.5296, -0.5782), length 110
  Sketch82 on start face of Pocket15, origin (2102.3549, 0, -2376.2799), H (0, 1, 0), V (0.749, 0, 0.6626)
    line L1 (90, 3865.6149) -> (50, 3865.6149)
    line L2 (50, 3865.6149) -> (90, 4009.6149)
    line L3 (90, 4009.6149) -> (90, 3865.6149)
    reference projected line E1 (90, 3865.6149) -> (90, 4009.6149) from edge [face of Pad57 from Sketch73.L3 | start face of Pocket15]
    reference projected line E2 (90, 3865.6149) -> (50, 3865.6149) from edge [start face of Pocket15 | face of Pocket14 from Sketch74.L3]
    reference projected line E4 (40, 3829.6149) -> (90, 4009.6149) from edge [start face of Pocket15 | face of Pocket15 from Sketch75.L1]
    line L4 (-90, 4009.6149) -> (-90, 3865.6149)
    line L5 (-90, 3865.6149) -> (-50, 3865.6149)
    line L6 (-50, 3865.6149) -> (-90, 4009.6149)
    reference projected line E5 (-90, 3865.6149) -> (-90, 4009.6149) from edge [start face of Pocket15 | face of Pad57 from Sketch73.L1]
    reference projected line E6 (90, 3865.6149) -> (50, 3865.6149) from edge [start face of Pocket15 | face of Pocket14 from Sketch74.L3]
    reference projected line E8 (-90, 4009.6149) -> (-40, 3829.6149) from edge [start face of Pocket15 | face of Pocket15 from Sketch75.L2]
    coincidence: L3 E1, L1 E2, L2 E4, L4 E5, L5 E6, L6 E8
    vertical: L4 V
    horizontal: L5 H
  Pocket19: profile Sketch82, direction (-0.6626, 0, 0.749), length 110
  Mirror30: of Pad59, Pad60, Pocket16, Pocket17, Pocket18, about zx-plane
  Sketch83 on face of Pad58, origin (280.9952, 0, 1170.4292), H (0, 1, 0), V (-0.9724, 0, 0.2334)
    line L1 (-74.1957, -4952.4074) -> (74.1914, -4953.2041)
    line L2 (74.1914, -4953.2041) -> (74.9968, -4803.2063)
    line L3 (74.9968, -4803.2063) -> (-75.0011, -4802.4009)
    line L4 (-75.0011, -4802.4009) -> (-74.1957, -4952.4074)
    reference projected line E1 (86.0205, -2749.9924) -> (63.5204, -6940.7224) from edge [face of Mirror2 | end face of Pad6]
    reference projected line E2 (-86.0205, -2749.9924) -> (-63.5204, -6940.7224) from edge [face of Mirror2 | face of Mirror2]
    distance L3 L1 = 150
    angle L3 L2 = 90
    length L3 = 150
    coincidence: L2 E1, L4 E2
  Pad61: profile Sketch83, direction (0.2334, 0, 0.9724), length 25, mirrored extent
  Sketch84 on end face of Pad61, origin (286.8313, 0, 1194.7384), H (0, 1, 0), V (-0.9724, 0, 0.2334)
    line L1 (-50, -4696.0528) -> (50, -4696.0528)
    line L2 (50, -4696.0528) -> (50, -4846.0528)
    line L3 (50, -4846.0528) -> (-50, -4846.0528)
    line L4 (-50, -4846.0528) -> (-50, -4696.0528)
    reference projected line E1 (50, -4795.5751) -> (50, -4709.5267) from edge [face of Pad56 | face of Pad56 from Sketch72.L4]
    reference projected line E2 (-50, -4795.5751) -> (-50, -4709.5267) from edge [face of Pad56 from Sketch72.L4 | face of Pad56]
    reference projected line E3 (-90, -4866.0528) -> (90, -4866.0528) from edge [face of Pocket14 from Sketch74.L3 | face of Pocket15]
    distance L2 E1 = 0
    distance L4 E2 = 0
    distance L1 L3 = 150
    distance L3 E3 = 20
    horizontal: L1 H, L3 H
    vertical: L2 V, L4 V
  Pad62: profile Sketch84, direction (0.2334, 0, 0.9724), length 50
  Sketch85 on face of Pocket15, origin (3003.024, 0, 2656.8512), H (0, 1, 0), V (-0.6626, 0, 0.749)
    line L1 (-65, -3152.791) -> (65, -3152.791)
    line L2 (65, -3152.791) -> (65, -3292.791)
    line L3 (65, -3292.791) -> (-65, -3292.791)
    line L4 (-65, -3292.791) -> (-65, -3152.791)
    reference projected line E1 (90, -3352.791) -> (90, -3172.791) from edge [face of Pocket15 | face of Pocket19]
    reference projected line E2 (-90, -3132.791) -> (90, -3132.791) from edge [face of Pocket14 from Sketch74.L3 | face of Pocket15]
    reference projected line E3 (-90, -3172.791) -> (-90, -3352.791) from edge [face of Pocket19 | face of Pocket15]
    reference projected line E4 (90, -3312.791) -> (-90, -3312.791) from edge [face of Pocket14 from Sketch74.L1 | face of Pocket15]
    distance L2 E1 = 25
    distance L1 E2 = 20
    distance L4 E3 = 25
    distance L3 E4 = 20
    horizontal: L1 H, L3 H
    vertical: L2 V, L4 V
  Pocket20: profile Sketch85, direction (-0.749, 0, -0.6626), length 40
  Sketch86 on start face of Pad51, origin (5308.6795, 0, -1274.5012), H (0, 1, 0), V (0.2334, 0, 0.9724)
    line L1 (-89.9125, 1155.4414) -> (90, 1155.4414)
    line L2 (90, 1155.4414) -> (90, 1125.4414)
    line L3 (90, 1125.4414) -> (-89.9125, 1125.4414)
    line L4 (-89.9125, 1125.4414) -> (-89.9125, 1155.4414)
    reference projected line E1 (71.473, 1145.4414) -> (-71.473, 1145.4414) from edge [start face of Pad51 | face of Mirror2]
    reference projected line E2 (71.473, 1145.4414) -> (-71.473, 1145.4414) from edge [start face of Pad51 | face of Mirror2]
    reference projected point E3 (0.0875, 1206.4414) from axis of face of Pad51 from Sketch66.A2
    reference intersected line E4 through (0, 0) direction (0, 1) from zx-plane
    distance L1 E1 = 10
    distance L3 E2 = 20
    distance L4 E3 = 90
    distance L2 E4 = 90
    horizontal: L1 H, L3 H
    vertical: L2 V, L4 V
  Pad63: profile Sketch86, direction (0.9724, 0, -0.2334), length 51, mirrored extent
  Sketch87 on end face of Pad1, origin (-2000, 0, 0), H (0, -1, 0), V (0, 0, 1)
    line L1 (-110, 460) -> (-90, 460)
    line L2 (-90, 460) -> (-90, 440)
    line L3 (-90, 440) -> (-110, 440)
    line L4 (-110, 440) -> (-110, 460)
    horizontal: L1 H, L3 H
    vertical: L2 V, L4 V
  Pad64: profile Sketch87, direction (1, 0, 0), length 51
  Mirror31: of Pad64, about zx-plane
  Sketch88 on face of Pad50 from Sketch64.L1, origin (0, 0, 480.931), H (1, 0, 0), V (0, 1, 0)
    line L1 (2880.11, 143.815) -> (2960.11, 143.815)
    line L2 (2960.11, 143.815) -> (2960.11, -143.815)
    line L3 (2960.11, -143.815) -> (2880.11, -143.815)
    line L4 (2880.11, -143.815) -> (2880.11, 143.815)
    reference projected line E1 (2945.11, 128.815) -> (3048.11, 128.815) from edge [face of Pad50 from Sketch64.L1 | face of Pad50 from Sketch64.L2]
    reference projected line E2 (2945.11, -128.815) -> (3048.11, -128.815) from edge [face of Pad50 from Sketch64.L4 | face of Pad50 from Sketch64.L1]
    reference projected line E3 (2945.11, 128.815) -> (2945.11, -128.815) from edge [start face of Pad50 | face of Pad50 from Sketch64.L1]
    distance L1 E1 = 15
    distance L3 E2 = 15
    distance L4 L2 = 80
